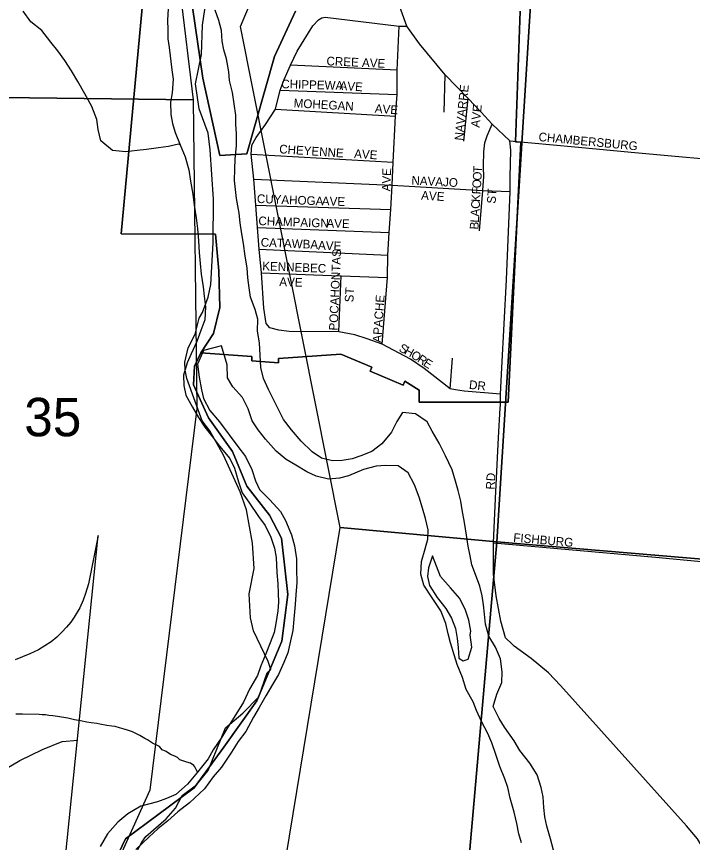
# Model space of a CAD drawing. Extents: x 8.5 to 81.5, y -1.2 to 22.4.
# Drawn here: x 53.317 to 54.054, y 15.95 to 16.85 of the extents above; entities that cross this region are included whole.
import ezdxf

# ---------------------------------------------------------------- set-up
doc = ezdxf.new("R2010")
doc.units = 0
for name, color, linetype in [('GM_X_City_Street', 7, 'Continuous'), ('GM_X_City_Street_Text', 7, 'Continuous'), ('GM_X_Corporation', 7, 'Continuous'), ('GM_X_Major_River', 7, 'Continuous'), ('GM_X_Minor_River', 7, 'Continuous'), ('GM_X_Rail_Line', 7, 'Continuous'), ('GM_X_Section', 7, 'Continuous'), ('GM_X_Section_Text', 7, 'Continuous'), ('GM_X_Township', 7, 'Continuous')]:
    doc.layers.add(name, color=color, linetype=linetype)

msp = doc.modelspace()

# ---------------------------------------------------------------- linework, layer by layer
at = {"layer": 'GM_X_City_Street'}
for points in [[(53.85493, 16.71506), (53.83572, 16.73309), (53.82373, 16.74626), (53.80958, 16.76105), (53.78449, 16.78694), (53.75643, 16.82055), (53.74242, 16.84002), (53.73642, 16.85677), (53.7341, 16.86459)], [(53.78965, 16.4449), (53.7616, 16.46679), (53.74648, 16.47709), (53.71566, 16.4934), (53.69949, 16.49917), (53.68605, 16.50373), (53.66848, 16.50702), (53.61451, 16.50731), (53.60304, 16.50866), (53.59342, 16.51113), (53.58911, 16.51606), (53.58683, 16.53257), (53.58417, 16.57095), (53.58183, 16.59697), (53.57982, 16.62052), (53.57789, 16.645), (53.57566, 16.67332), (53.57295, 16.70058), (53.57357, 16.71032), (53.57825, 16.71846), (53.58873, 16.73264), (53.59934, 16.74929), (53.6044, 16.77002), (53.60872, 16.78173), (53.61581, 16.79721), (53.6229, 16.81269), (53.64004, 16.84007), (53.64621, 16.84661), (53.65003, 16.84895), (53.65374, 16.84969), (53.73431, 16.83975), (53.74242, 16.84002)], [(53.71566, 16.4934), (53.72138, 16.56587), (53.72194, 16.59025), (53.72338, 16.61518), (53.72517, 16.63998), (53.72643, 16.6666), (53.72755, 16.69168), (53.73021, 16.74184), (53.73216, 16.76551), (53.73201, 16.79211), (53.73431, 16.83975)], [(53.73201, 16.79211), (53.61581, 16.79721)], [(53.78317, 16.74635), (53.78449, 16.78694)], [(53.6044, 16.77002), (53.73216, 16.76551)], [(53.80476, 16.71449), (53.80958, 16.76105)], [(53.59934, 16.74929), (53.73021, 16.74184)], [(53.82611, 16.68559), (53.82606, 16.68768), (53.82663, 16.703), (53.82771, 16.71259), (53.83004, 16.72032), (53.83572, 16.73309)], [(53.84431, 16.4235), (53.84451, 16.42711), (53.84479, 16.43875), (53.84622, 16.4677), (53.85104, 16.56336), (53.85502, 16.65986), (53.8553, 16.67547), (53.85599, 16.70477), (53.85493, 16.71506)], [(53.85493, 16.71506), (53.92574, 16.70845), (53.99114, 16.70236), (54.11111, 16.69126), (54.18299, 16.68483), (54.27096, 16.67694), (54.28352, 16.67634)], [(53.57295, 16.70058), (53.72755, 16.69168)], [(53.8218, 16.617), (53.82521, 16.661), (53.82635, 16.67661), (53.82611, 16.68559)], [(53.57566, 16.67332), (53.72643, 16.6666), (53.82521, 16.661), (53.85502, 16.65986)], [(53.57789, 16.645), (53.72517, 16.63998)], [(53.57982, 16.62052), (53.72338, 16.61518)], [(53.58183, 16.59697), (53.72194, 16.59025)], [(53.58417, 16.57095), (53.66993, 16.56789)], [(53.66848, 16.50702), (53.6711, 16.56785)], [(53.66993, 16.56789), (53.6711, 16.56785), (53.72138, 16.56587)], [(53.78965, 16.4449), (53.79217, 16.47797)], [(53.84479, 16.43875), (53.80491, 16.44236), (53.79571, 16.44357), (53.78965, 16.4449)], [(53.85738, 16.16643), (53.85015, 16.17356), (53.84488, 16.19143), (53.84001, 16.21922), (53.83685, 16.2429), (53.83687, 16.27708), (53.83928, 16.32536), (53.84253, 16.39163), (53.84431, 16.4235)], [(53.83687, 16.27708), (54.01347, 16.26148)], [(54.01347, 16.26148), (54.27044, 16.23693), (54.3281, 16.23637), (54.33022, 16.23603)], [(53.98932, 15.38116), (54.04647, 15.6717), (54.06235, 15.85698), (54.06903, 15.9284), (54.06842, 15.93726), (54.06647, 15.94259), (54.05925, 15.95437), (54.04717, 15.96843), (53.91, 16.12149), (53.89682, 16.13519), (53.87801, 16.15093), (53.85956, 16.16427), (53.85738, 16.16643)], [(53.20224, 15.85881), (53.20255, 15.94581), (53.20611, 15.9572), (53.21393, 15.96928), (53.24201, 15.99125), (53.28154, 16.01695), (53.32067, 16.03971), (53.34557, 16.05181), (53.36692, 16.06034), (53.384, 16.06177)]]:
    msp.add_lwpolyline(points, dxfattribs=at)
at = {"layer": 'GM_X_Corporation'}
for points in [[(53.41872, 15.91772), (53.43605, 15.95427), (53.47107, 15.98064), (53.5107, 16.00997), (53.54299, 16.05425), (53.57918, 16.10491), (53.6065, 16.16977), (53.61306, 16.22055), (53.60613, 16.2822), (53.59289, 16.30711), (53.56835, 16.33867), (53.55266, 16.37653), (53.52632, 16.41306), (53.51021, 16.44903), (53.51132, 16.46952), (53.51803, 16.48384), (53.53185, 16.50519), (53.53869, 16.53318), (53.53774, 16.57342), (53.53412, 16.61332), (53.43128, 16.61363), (53.48662, 17.20826)], [(53.48662, 17.20826), (53.43128, 16.61363), (53.53412, 16.61332), (53.53774, 16.57342), (53.53869, 16.53318), (53.53185, 16.50519), (53.51803, 16.48384), (53.57376, 16.47994), (53.57376, 16.47521), (53.60257, 16.47319), (53.60257, 16.47792), (53.67059, 16.48268), (53.70458, 16.46825), (53.70273, 16.4639), (53.73847, 16.44873), (53.74032, 16.45309), (53.75598, 16.4433), (53.75598, 16.43005), (53.85289, 16.43005), (53.86686, 16.71338), (53.86114, 16.71386), (53.86616, 16.85622)], [(53.86616, 16.85622), (53.86114, 16.71386), (53.86686, 16.71338), (53.85289, 16.43005), (53.75598, 16.43005), (53.75598, 16.4433), (53.74032, 16.45309), (53.73847, 16.44873), (53.70273, 16.4639), (53.70458, 16.46825), (53.67059, 16.48268), (53.60257, 16.47792), (53.60257, 16.47319), (53.57376, 16.47521), (53.57376, 16.47994), (53.51803, 16.48384), (53.51132, 16.46952), (53.51021, 16.44903), (53.52632, 16.41306), (53.55266, 16.37653), (53.56835, 16.33867), (53.59289, 16.30711), (53.60613, 16.2822), (53.61306, 16.22055), (53.6065, 16.16977), (53.57918, 16.10491), (53.54299, 16.05425), (53.5107, 16.00997), (53.47107, 15.98064), (53.43605, 15.95427), (53.41872, 15.91772)], [(53.50888, 16.86072), (53.52009, 16.78306), (53.53882, 16.69906), (53.56807, 16.7006), (53.59836, 16.80689), (53.62137, 16.85622)], [(53.62137, 16.85622), (53.59836, 16.80689), (53.56807, 16.7006), (53.53882, 16.69906), (53.52009, 16.78306), (53.50888, 16.86072)]]:
    msp.add_lwpolyline(points, dxfattribs=at)
at = {"layer": 'GM_X_Major_River'}
for points in [[(53.48245, 16.85865), (53.48183, 16.8465), (53.482, 16.83586), (53.48218, 16.82598), (53.48352, 16.81645), (53.48646, 16.79246), (53.48778, 16.78217), (53.48673, 16.76738), (53.48501, 16.75715), (53.4855, 16.74346), (53.48721, 16.73393), (53.49006, 16.72399), (53.49549, 16.71059), (53.50093, 16.69756), (53.50483, 16.68342), (53.50686, 16.67084), (53.50925, 16.65673), (53.51091, 16.64492), (53.51292, 16.6312), (53.51459, 16.61939), (53.51547, 16.60607), (53.51635, 16.59314), (53.51726, 16.58134), (53.51855, 16.56954), (53.52056, 16.55582), (53.52187, 16.54553), (53.52317, 16.53411), (53.52251, 16.52006), (53.5181, 16.50838), (53.51369, 16.49631), (53.50772, 16.48275), (53.50335, 16.47296), (53.49929, 16.45975), (53.49945, 16.44835), (53.5019, 16.43766), (53.50886, 16.4246), (53.51548, 16.41344), (53.52249, 16.40304), (53.53064, 16.39261), (53.53841, 16.3822), (53.54954, 16.36867), (53.55466, 16.35831), (53.5593, 16.34339), (53.56325, 16.33153), (53.57026, 16.32113), (53.58097, 16.30571), (53.58837, 16.29568), (53.5942, 16.28303), (53.59853, 16.27116), (53.60022, 16.26087), (53.60104, 16.24451), (53.60194, 16.23233), (53.6025, 16.22206), (53.60269, 16.21218), (53.60212, 16.20269), (53.59995, 16.18906), (53.59786, 16.17922), (53.59346, 16.16791), (53.58904, 16.15584), (53.58347, 16.14303), (53.57984, 16.13247), (53.57119, 16.11745), (53.56446, 16.10352), (53.55621, 16.09001), (53.54758, 16.07613), (53.54091, 16.06524), (53.53152, 16.05138), (53.52601, 16.04161), (53.51433, 16.02703), (53.50343, 16.01395), (53.49068, 16.00281), (53.48071, 15.99845), (53.47077, 15.99486), (53.45281, 15.9899), (53.4386, 15.98183), (53.42778, 15.97255), (53.41651, 15.95986), (53.40826, 15.94597)], [(53.80774, 16.28514), (53.80535, 16.29924), (53.80296, 16.31297), (53.80125, 16.3225), (53.79844, 16.33396), (53.7956, 16.34428), (53.79205, 16.35651), (53.78475, 16.37185), (53.77781, 16.38567), (53.77009, 16.39875), (53.76458, 16.40874), (53.75184, 16.41736), (53.73781, 16.41878), (53.73154, 16.40903), (53.72599, 16.39737), (53.71549, 16.38466), (53.70431, 16.37653), (53.69244, 16.37183), (53.68288, 16.36861), (53.6722, 16.36655), (53.66156, 16.36638), (53.64946, 16.36929), (53.63934, 16.37596), (53.62741, 16.3876), (53.61702, 16.39997), (53.60812, 16.41117), (53.60301, 16.42153), (53.59788, 16.43152), (53.59168, 16.44418), (53.58621, 16.45607), (53.58341, 16.46791), (53.58292, 16.48159), (53.58204, 16.49491), (53.58001, 16.50749), (53.58027, 16.52078), (53.57743, 16.5311), (53.57238, 16.5445), (53.57068, 16.55479), (53.56938, 16.56584), (53.56845, 16.5765), (53.56642, 16.58946), (53.56441, 16.60317), (53.56238, 16.61575), (53.56106, 16.62566), (53.55974, 16.63595), (53.55702, 16.65196), (53.55475, 16.67176), (53.55499, 16.68391), (53.55559, 16.6953), (53.557, 16.70933), (53.55689, 16.72301), (53.55633, 16.7329), (53.55614, 16.74278), (53.55449, 16.75535), (53.55245, 16.76755), (53.54929, 16.78053), (53.54872, 16.79004), (53.54595, 16.80416), (53.54311, 16.81409), (53.5414, 16.82363), (53.54048, 16.83504), (53.53766, 16.84612), (53.5337, 16.85722)], [(53.54063, 16.49159), (53.5211, 16.48666), (53.51434, 16.4716), (53.51634, 16.4575), (53.51873, 16.44377), (53.52082, 16.43423), (53.52778, 16.42117), (53.53856, 16.40879), (53.55854, 16.38178), (53.56668, 16.37098), (53.57362, 16.35678), (53.57756, 16.34454), (53.58193, 16.33495), (53.5931, 16.32371), (53.60501, 16.31092), (53.61052, 16.30131), (53.61705, 16.2856), (53.62023, 16.27376), (53.62223, 16.25966), (53.62239, 16.24825), (53.62287, 16.23381), (53.62146, 16.22016), (53.62088, 16.20991), (53.61941, 16.1936), (53.61842, 16.18146), (53.61591, 16.17011), (53.613, 16.15725), (53.60861, 16.1467), (53.60266, 16.13352), (53.59636, 16.12263), (53.5889, 16.11024), (53.58181, 16.09747), (53.57553, 16.08696), (53.56725, 16.07155), (53.55867, 16.06032), (53.5516, 16.04869), (53.54065, 16.03257), (53.5317, 16.02211), (53.52195, 16.00901), (53.50569, 15.99376), (53.49296, 15.98376), (53.48213, 15.9741), (53.47132, 15.9652), (53.46166, 15.95666), (53.44733, 15.94289)], [(53.86761, 15.94992), (53.86477, 15.95985), (53.86234, 15.9713), (53.85954, 15.98352), (53.85528, 15.99881), (53.85247, 16.01026), (53.84924, 16.01983), (53.84381, 16.03324), (53.8395, 16.04624), (53.83519, 16.05887), (53.83084, 16.06922), (53.82424, 16.08152), (53.81841, 16.09417), (53.8148, 16.10375), (53.80709, 16.1172), (53.80317, 16.1302), (53.79737, 16.14438), (53.79416, 16.15508), (53.79024, 16.16808), (53.78777, 16.17763), (53.78495, 16.18909), (53.77953, 16.20288), (53.77031, 16.21713), (53.76109, 16.23099), (53.7579, 16.24283), (53.75855, 16.2565), (53.76262, 16.27048), (53.76549, 16.28106), (53.76568, 16.29093), (53.76289, 16.30353), (53.75969, 16.31461), (53.75613, 16.32684), (53.75108, 16.34024), (53.74412, 16.3533), (53.73325, 16.36074), (53.7192, 16.36103), (53.70931, 16.36047), (53.69519, 16.35696), (53.6791, 16.35007), (53.66916, 16.34723), (53.65737, 16.34633), (53.64376, 16.34965), (53.6336, 16.35442), (53.62158, 16.3615), (53.61106, 16.36779), (53.60023, 16.37675), (53.58871, 16.38991), (53.58055, 16.39995), (53.57391, 16.40997), (53.56961, 16.42297), (53.56339, 16.43526), (53.55298, 16.44687), (53.5471, 16.45687), (53.54662, 16.47094), (53.54063, 16.49159)], [(53.90241, 15.94199), (53.89924, 15.95459), (53.89495, 15.96836), (53.89287, 15.97828), (53.89193, 15.98856), (53.89102, 16.00036), (53.88894, 16.01028), (53.88465, 16.02405), (53.87654, 16.03675), (53.8658, 16.05065), (53.85955, 16.06104), (53.84883, 16.07608), (53.84332, 16.08569), (53.83674, 16.09874), (53.84079, 16.11196), (53.84599, 16.12477), (53.8466, 16.13654), (53.8446, 16.15064), (53.83915, 16.16329), (53.83178, 16.17522), (53.82824, 16.18821), (53.82732, 16.19924), (53.826, 16.20953), (53.82467, 16.21906), (53.82222, 16.22975), (53.81753, 16.24238), (53.81356, 16.2531), (53.81147, 16.26264), (53.8094, 16.27332), (53.80774, 16.28514)], [(53.77045, 16.26272), (53.76602, 16.24989), (53.76507, 16.24041), (53.76715, 16.23049), (53.77563, 16.2174), (53.78489, 16.20543), (53.79115, 16.19504), (53.79548, 16.18355), (53.79755, 16.17287), (53.79849, 16.16297), (53.7994, 16.15118), (53.80388, 16.14844), (53.80926, 16.15022), (53.81332, 16.16343), (53.81168, 16.17677)], [(53.81168, 16.17677), (53.81214, 16.18056), (53.8101, 16.19276), (53.80651, 16.20347), (53.8003, 16.21613), (53.79027, 16.22774), (53.77912, 16.24012), (53.77045, 16.26272)]]:
    msp.add_lwpolyline(points, dxfattribs=at)
at = {"layer": 'GM_X_Minor_River'}
for points in [[(53.49549, 16.71059), (53.49361, 16.71138), (53.48292, 16.70894), (53.47187, 16.70727), (53.45892, 16.70564), (53.44864, 16.70433), (53.43646, 16.70306), (53.42167, 16.7045), (53.40897, 16.71502), (53.40617, 16.72724), (53.40486, 16.73828), (53.39944, 16.75245), (53.39174, 16.76628), (53.38403, 16.77974), (53.37704, 16.79128), (53.37004, 16.80244), (53.36226, 16.81286), (53.35448, 16.82252), (53.34485, 16.83526), (53.33288, 16.84462), (53.32437, 16.85619)], [(53.51433, 16.02703), (53.51156, 16.03296), (53.51031, 16.03424), (53.50693, 16.03686), (53.50278, 16.03808), (53.49525, 16.04052), (53.49265, 16.04323), (53.48963, 16.04443), (53.48512, 16.04642), (53.48025, 16.04956), (53.47612, 16.05154), (53.47316, 16.05502), (53.46526, 16.0586), (53.46002, 16.06213), (53.45702, 16.06371), (53.45177, 16.06686), (53.44351, 16.0712), (53.43824, 16.07283), (53.43446, 16.07405), (53.42956, 16.07528), (53.42466, 16.0769), (53.42125, 16.07735), (53.41557, 16.07785), (53.40802, 16.07952), (53.40461, 16.07997), (53.39856, 16.08085), (53.39402, 16.0817), (53.38684, 16.08299), (53.38041, 16.08425), (53.37324, 16.08592), (53.36189, 16.08767), (53.35697, 16.08853), (53.35243, 16.089), (53.34865, 16.08946), (53.34523, 16.08952), (53.34183, 16.08997), (53.32362, 16.09034), (53.31641, 16.0901)]]:
    msp.add_lwpolyline(points, dxfattribs=at)
at = {"layer": 'GM_X_Rail_Line'}
for points in [[(53.40637, 16.28505), (53.39565, 16.2324), (53.39247, 16.22175), (53.3897, 16.21442), (53.38624, 16.20612), (53.38002, 16.19587), (53.3763, 16.19068), (53.37169, 16.18509), (53.3666, 16.17951), (53.36121, 16.17431), (53.35513, 16.16922), (53.34808, 16.16462), (53.34112, 16.16031), (53.33182, 16.15599), (53.31575, 16.14943)], [(53.42073, 14.45055), (53.42748, 14.55457), (53.43258, 14.6331), (53.43038, 14.7068), (53.43028, 14.76587), (53.42326, 14.86198), (53.4166, 14.93195), (53.39247, 15.18685), (53.38185, 15.2812), (53.36704, 15.41986), (53.35229, 15.55177), (53.3481, 15.59619), (53.34547, 15.6552), (53.35059, 15.73656), (53.35358, 15.76861), (53.35901, 15.82032), (53.40637, 16.28505)]]:
    msp.add_lwpolyline(points, dxfattribs=at)
at = {"layer": 'GM_X_Section'}
for points in [[(53.22721, 17.83517), (53.85767, 17.82864), (53.58921, 17.24628), (53.49556, 16.87689), (53.50964, 16.7596), (53.21242, 16.76328)], [(53.74453, 17.32934), (53.90559, 17.31458), (53.84071, 16.2781), (53.66982, 16.29381), (53.56113, 16.83968), (53.65228, 17.05536)], [(53.90559, 17.31458), (54.89877, 17.22287), (54.83971, 16.19386), (53.84071, 16.2781)], [(53.21242, 16.76328), (53.50964, 16.7596), (53.51356, 16.42322), (53.4626, 16.00759), (53.38319, 15.83221), (53.38111, 15.76219), (53.20654, 15.7628)], [(53.84071, 16.2781), (53.754, 15.28899), (53.50821, 15.30912), (53.66982, 16.29381)], [(54.83971, 16.19386), (54.76697, 15.20261), (54.63198, 15.21347), (54.5739, 15.42853), (54.51097, 15.48614), (54.47146, 15.49976), (54.30174, 15.51695), (54.1688, 15.47589), (54.05647, 15.42346), (53.89958, 15.2768), (53.754, 15.28899), (53.84071, 16.2781)]]:
    msp.add_lwpolyline(points, close=True, dxfattribs=at)
at = {"layer": 'GM_X_Township'}
msp.add_lwpolyline([(53.43881, 15.92281), (53.45379, 15.95083), (53.458, 15.95688), (53.48013, 15.97613), (53.49045, 15.98785), (53.49774, 16.00148), (53.51337, 16.01317), (53.52599, 16.02905), (53.54489, 16.07527), (53.56395, 16.09149), (53.58114, 16.10925), (53.59042, 16.1354), (53.59423, 16.13879), (53.59164, 16.14754), (53.57556, 16.18103), (53.57225, 16.1951), (53.57091, 16.2213), (53.57603, 16.24899), (53.57432, 16.27671), (53.56774, 16.31281), (53.56105, 16.33259), (53.54275, 16.37254), (53.52776, 16.39882), (53.5195, 16.40987), (53.50275, 16.45589), (53.50091, 16.46501), (53.50059, 16.47375), (53.50411, 16.48929), (53.5118, 16.50444), (53.51609, 16.52188), (53.51992, 16.52793), (53.5261, 16.5446), (53.52885, 16.55825), (53.53144, 16.60379), (53.53176, 16.65124), (53.52834, 16.70517), (53.52618, 16.7234), (53.51613, 16.74964), (53.51214, 16.777), (53.5188, 16.80885), (53.51978, 16.84111), (53.52732, 16.89004)], dxfattribs=at)

# ---------------------------------------------------------------- texts
at = {"layer": 'GM_X_City_Street_Text'}
for s, height, rotation, p in [('CREE AVE', 0.00947, 357.47209, (53.65486, 16.79728)), ('CHIPPEWA', 0.00947, 358.38741, (53.60567, 16.77228)), ('AVE', 0.00947, 356.05688, (53.66907, 16.77061)), ('NAVARRE', 0.00947, 84.03531, (53.80384, 16.71486)), ('MOHEGAN', 0.00947, 356.77414, (53.61905, 16.75145)), ('AVE', 0.00947, 355.90884, (53.70741, 16.74562)), ('AVE', 0.00947, 84.09025, (53.82171, 16.72901)), ('CHAMBERSBURG', 0.0094697, 354.53716, (53.88578, 16.71478)), ('CHEYENNE', 0.00947, 356.18515, (53.60324, 16.70145)), ('AVE', 0.00947, 356.05688, (53.68491, 16.69645)), ('AVE', 0.00947, 88.02609, (53.72467, 16.65973)), ('T', 0.00947, 87.08716, (53.82429, 16.67978)), ('NAVAJO', 0.00947, 356.93518, (53.74738, 16.66728)), ('O', 0.00947, 86.50234, (53.82377, 16.67136)), ('O', 0.00947, 86.47955, (53.82326, 16.66304)), ('AVE', 0.00947, 356.05688, (53.75795, 16.65103)), ('F', 0.00947, 86.50654, (53.82285, 16.65639)), ('ST', 0.00947, 86.42535, (53.83926, 16.64627)), ('CUYAHOGA', 0.00947, 357.82365, (53.57902, 16.64729)), ('AVE', 0.00947, 358.02611, (53.64984, 16.64479)), ('C', 0.00947, 86.47668, (53.82188, 16.64058)), ('K', 0.00947, 86.50234, (53.82234, 16.64807)), ('A', 0.00947, 86.50234, (53.82137, 16.63226)), ('CHAMPAIGN', 0.00947, 357.95311, (53.58068, 16.62312)), ('L', 0.00947, 86.47308, (53.82096, 16.6256)), ('AVE', 0.00947, 358.02611, (53.65484, 16.62062)), ('B', 0.00947, 86.50091, (53.82051, 16.61811)), ('CATAWBA', 0.00947, 357.54744, (53.58319, 16.59978)), ('AVE', 0.00947, 358.02611, (53.64568, 16.59645)), ('POCAHONTAS', 0.00947, 87.53614, (53.66717, 16.50808)), ('KENNEBEC', 0.00947, 357.67966, (53.58486, 16.57395)), ('AVE', 0.00947, 358.02611, (53.60345, 16.55684)), ('ST', 0.00947, 86.4126, (53.68426, 16.53876)), ('APACHE', 0.00947, 85.91271, (53.71467, 16.4948)), ('S', 0.00947, 332.01751, (53.73311, 16.48625)), ('H', 0.00947, 331.49943, (53.73898, 16.48313)), ('O', 0.00947, 327.8255, (53.74617, 16.47923)), ('R', 0.00947, 326.53222, (53.75317, 16.47483)), ('E', 0.00947, 327.57384, (53.75959, 16.47059)), ('DR', 0.00947, 353.98201, (53.80997, 16.44477)), ('RD', 0.00947, 86.98901, (53.83812, 16.33476)), ('FISHBURG', 0.00947, 355.02985, (53.85827, 16.27812))]:
    msp.add_text(s, height=height, rotation=rotation, dxfattribs=at).set_placement(p)
at = {"layer": 'GM_X_Section_Text'}
msp.add_text('35', height=0.041856, rotation=0.00001, dxfattribs=at).set_placement((53.32562, 16.39306))

doc.saveas('drawing.dxf')
